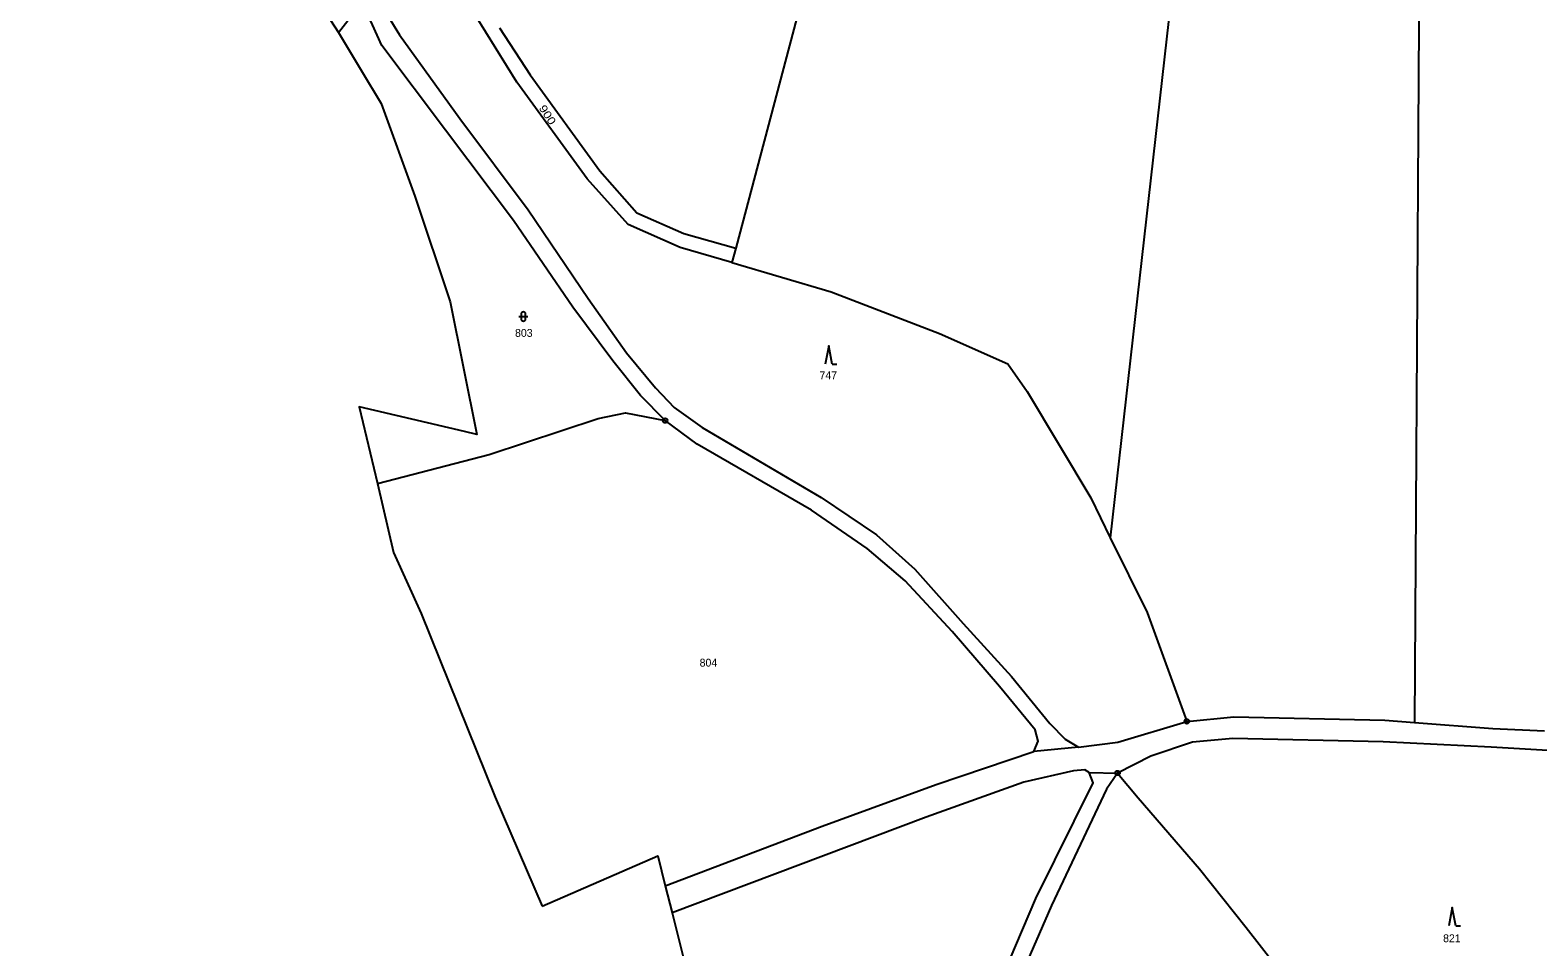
# Model space of a CAD drawing. Extents: x -754445 to -751443, y -1030748 to -1028224.
# Drawn here: x -752777.7 to -752451.7, y -1030202.9 to -1030004.6 of the extents above; entities that cross this region are included whole.
import ezdxf
from ezdxf.enums import TextEntityAlignment as Align

# ---------------------------------------------------------------- set-up
doc = ezdxf.new("R2010")
doc.units = 0
doc.header["$LTSCALE"] = 0.68
for name, color, linetype, lineweight in [('1', 7, 'Continuous', 25), ('3', 7, 'Continuous', 25), ('8', 7, 'Continuous', 25)]:
    doc.layers.add(name, color=color, linetype=linetype, lineweight=lineweight)
doc.layers.add('2', color=7, linetype='Continuous')

msp = doc.modelspace()

# ---------------------------------------------------------------- linework, layer by layer
at = {"layer": '1'}
for p, q in [((-752625.1, -1030051.81), (-752625.92, -1030054.91)), ((-752551, -1030159.68), (-752560.64, -1030160.68)), ((-752548.68, -1030165.22), (-752542.54, -1030165.3)), ((-752640.36, -1030189.71), (-752638.88, -1030195.57))]:
    msp.add_line(p, q, dxfattribs=at)
for points in [[(-752541.89, -1029737.4), (-752583.5, -1029894.61), (-752625.1, -1030051.81)], [(-752507.16, -1029786.29), (-752525.64, -1029950.35), (-752544.12, -1030114.41)], [(-752476.09, -1029805.42), (-752477.23, -1029979.89), (-752478.36, -1030154.36)], [(-752777.69, -1029878.65), (-752760.9, -1029912.8), (-752737.38, -1029958.33), (-752725.32, -1029983.05), (-752711, -1030005.14), (-752705.94, -1029998.68)], [(-752706.07, -1029970.87), (-752707.71, -1029973.53), (-752703.43, -1029990.55), (-752702.35, -1029996.49), (-752700.34, -1030001.56), (-752697.79, -1030005.67), (-752684.78, -1030023.76), (-752670, -1030043.5), (-752657, -1030062.67), (-752648.73, -1030074.39), (-752642.45, -1030082.01), (-752638.39, -1030086.24), (-752632.35, -1030090.6), (-752606.65, -1030105.73), (-752594.7, -1030113.8), (-752586.38, -1030121.23), (-752575.93, -1030132.99), (-752565.47, -1030144.4), (-752557.22, -1030154.57), (-752553.91, -1030158), (-752551, -1030159.68)], [(-752625.92, -1030054.91), (-752637.1, -1030051.61), (-752648.35, -1030046.67), (-752657.25, -1030036.79), (-752672.47, -1030015.92), (-752683.6, -1029997.8), (-752691.15, -1029985.87), (-752697.01, -1029979.48), (-752706.07, -1029970.87)], [(-752640.37, -1030089.07), (-752645.68, -1030083.62), (-752651.71, -1030076.16), (-752660.34, -1030064.57), (-752673.14, -1030045.78), (-752687.89, -1030026.27), (-752701.65, -1030007.93), (-752703.69, -1030003.46), (-752705.94, -1029998.68)], [(-752711, -1030005.14), (-752706.06, -1030013.42), (-752701.81, -1030020.53), (-752694.5, -1030040.56), (-752686.89, -1030063.39), (-752681.08, -1030092.08), (-752683.78, -1030091.44), (-752706.52, -1030086.07), (-752702.61, -1030102.71)], [(-752676.19, -1030004.13), (-752669.55, -1030014.28), (-752654.51, -1030035.06), (-752646.49, -1030044.15), (-752636.32, -1030048.58), (-752625.1, -1030051.81)], [(-752625.92, -1030054.91), (-752604.44, -1030061.25), (-752581.03, -1030070.22), (-752566.28, -1030076.8), (-752562.09, -1030082.82), (-752548.35, -1030105.81), (-752544.12, -1030114.41)], [(-752702.61, -1030102.71), (-752678.45, -1030096.41), (-752654.88, -1030088.61), (-752648.92, -1030087.43), (-752640.37, -1030089.07)], [(-752560.64, -1030160.68), (-752559.71, -1030158.39), (-752560.34, -1030155.97), (-752568.08, -1030146.56), (-752578.32, -1030134.69), (-752588.48, -1030123.74), (-752596.71, -1030116.73), (-752608.7, -1030108.48), (-752633.47, -1030094.2), (-752640.37, -1030089.07)], [(-752702.61, -1030102.71), (-752699.11, -1030117.61), (-752693.1, -1030130.8), (-752677.15, -1030170.54), (-752666.96, -1030194.07)], [(-752544.12, -1030114.41), (-752536.14, -1030130.62), (-752527.55, -1030154.13)], [(-752527.55, -1030154.13), (-752517.42, -1030153.18), (-752484.73, -1030153.87), (-752478.36, -1030154.36)], [(-752551, -1030159.68), (-752542.52, -1030158.63), (-752527.55, -1030154.13)], [(-752478.36, -1030154.36), (-752461.37, -1030155.68), (-752450.21, -1030156.16)], [(-752444.34, -1030160.32), (-752448.3, -1030160.52), (-752461.79, -1030159.74), (-752485.11, -1030158.54), (-752517.65, -1030157.86), (-752526.32, -1030158.62), (-752535.32, -1030161.63), (-752542.54, -1030165.3)], [(-752640.36, -1030189.71), (-752606.45, -1030176.82), (-752581.77, -1030167.79), (-752560.64, -1030160.68)], [(-752542.54, -1030165.3), (-752544.93, -1030168.82), (-752556.85, -1030193.93), (-752565.3, -1030213.51), (-752574.65, -1030236.38), (-752584.69, -1030257.64), (-752603.15, -1030291.99), (-752617.15, -1030319.03), (-752641.57, -1030364.09), (-752659.49, -1030397), (-752677.41, -1030426.88), (-752682.78, -1030437.4)], [(-752548.68, -1030165.22), (-752549.63, -1030164.59), (-752552.04, -1030164.83), (-752562.79, -1030167.3), (-752583.94, -1030174.88), (-752638.88, -1030195.57)], [(-752615.8, -1030308.07), (-752606.48, -1030290.23), (-752587.74, -1030255.95), (-752578.15, -1030235.24), (-752568.65, -1030212.24), (-752560.25, -1030192.46), (-752547.81, -1030167.45), (-752548.68, -1030165.22)], [(-752542.54, -1030165.3), (-752538.08, -1030170.66), (-752524.8, -1030186.04), (-752514.75, -1030198.69), (-752492.51, -1030227.21), (-752483.79, -1030237.62), (-752470.22, -1030251.01), (-752462.26, -1030258.8), (-752457.23, -1030265.25), (-752454.91, -1030269.53), (-752453.11, -1030274.28)], [(-752666.96, -1030194.07), (-752641.99, -1030183.22), (-752640.36, -1030189.71)], [(-752638.88, -1030195.57), (-752634.67, -1030212.3), (-752629.44, -1030248.38), (-752626.95, -1030262.96), (-752622.25, -1030281.65), (-752615.8, -1030308.07)]]:
    msp.add_lwpolyline(points, dxfattribs=at)
at = {"layer": '3'}
for p, q in [((-752672.041, -1030066.561), (-752670.039, -1030066.561)), ((-752671.541, -1030066.061), (-752671.541, -1030067.062)), ((-752670.539, -1030067.062), (-752670.539, -1030066.061)), ((-752604.24, -1030076.91), (-752603.244, -1030076.91)), ((-752469.41, -1030198.38), (-752468.414, -1030198.38))]:
    msp.add_line(p, q, dxfattribs=at)
for points in [[(-752604.24, -1030076.91), (-752604.99, -1030072.91), (-752605.74, -1030076.91)], [(-752469.41, -1030198.38), (-752470.16, -1030194.38), (-752470.91, -1030198.38)]]:
    msp.add_lwpolyline(points, dxfattribs=at)
for centre, start, end in [((-752671.04, -1030066.0609), 0, 180), ((-752671.04, -1030067.0609), 180, 359.98789)]:
    msp.add_arc(centre, 0.5, start, end, dxfattribs=at)
at = {"layer": '8'}
for centre, radius in [((-752640.37, -1030089.0699), 0.5), ((-752640.37, -1030089.0699), 0.0303), ((-752527.55, -1030154.1299), 0.5), ((-752527.55, -1030154.1299), 0.0303), ((-752542.54, -1030165.2999), 0.5), ((-752542.54, -1030165.2999), 0.0303)]:
    msp.add_circle(centre, radius, dxfattribs=at)

# ---------------------------------------------------------------- texts
at = {"layer": '2', "width": 1.2}
msp.add_text('900', height=1.7, rotation=303, dxfattribs=at).set_placement((-752666.5269, -1030023.4101), align=Align.CENTER)
at = {"layer": '2'}
for s, p in [('803', (-752670.939, -1030070.966)), ('747', (-752605.099, -1030080.126)), ('804', (-752631.019, -1030142.286)), ('821', (-752470.249, -1030201.896))]:
    msp.add_text(s, height=1.7, dxfattribs=at).set_placement(p, align=Align.CENTER)

doc.saveas('drawing.dxf')
